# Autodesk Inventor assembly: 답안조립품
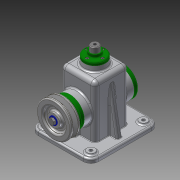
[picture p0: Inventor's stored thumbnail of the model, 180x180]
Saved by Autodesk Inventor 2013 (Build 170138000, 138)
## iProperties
Created: 2016-01
Part Number: 답안조립품
Document SubType Name: Assembly
Designer: User
Author: User
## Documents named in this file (19)
- C:\Users\User\Desktop\460126V1004\답안조립품.iam
- C:\Users\User\Desktop\460126V1004\본체.ipt
- C:\Users\User\Desktop\460126V1004\뒤커버.ipt
- C:\Users\User\Desktop\460126V1004\앞커버.ipt
- C:\Users\User\Desktop\460126V1004\상부부시.ipt
- C:\Users\User\Desktop\460126V1004\베어링 15 x 35 x 11.ipt
- C:\Users\User\Desktop\460126V1004\오일실 15 25 7.ipt
- C:\Users\User\Desktop\460126V1004\편심축.ipt
- C:\Users\User\Desktop\460126V1004\키 5 x 5 x 14.ipt
- C:\Users\User\Desktop\460126V1004\멈춤링 15 x 1.ipt
- C:\Users\User\Desktop\460126V1004\V-벨트풀리.ipt
- C:\Users\User\Desktop\460126V1004\와셔.ipt
- C:\Users\User\Desktop\460126V1004\볼트 M6 x 12.ipt
- C:\Users\User\Desktop\460126V1004\링크.ipt
- C:\Users\User\Desktop\460126V1004\고정핀.ipt
- C:\Users\User\Desktop\460126V1004\멈춤링 6 x 5.ipt
- C:\Users\User\Desktop\460126V1004\슬라이드바.ipt
- C:\Users\User\Desktop\460126V1004\볼트 M4 x 10.ipt
- C:\Users\User\Desktop\460126V1004\볼트 M3 x 8.ipt
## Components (15 placed, 5 different names)
1. V-벨트풀리:1
2. ISO 4018 M6 x 12:1 — 각도:2
3. 고정핀:1
4. ISO 4762 M4 x 10:1
5. ISO 4762 M4 x 10:3
6. ISO 4762 M4 x 10:4
7. ISO 4762 M4 x 10:5
8. ISO 4762 M4 x 10:2
9. ISO 4762 M4 x 10:6
10. ISO 4762 M4 x 10:7
11. ISO 4762 M4 x 10:8
12. ISO 4762 M3 x 8:1
13. ISO 4762 M3 x 8:2
14. ISO 4762 M3 x 8:3
15. ISO 4762 M3 x 8:4
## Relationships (1: Angle 1)
- 각도:2 [Angle]: ISO 4018 M6 x 12:1
